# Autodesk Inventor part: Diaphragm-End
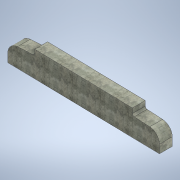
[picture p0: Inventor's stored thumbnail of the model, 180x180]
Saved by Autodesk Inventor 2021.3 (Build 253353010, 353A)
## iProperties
Created: 2021-10
Part Number: Diaphragm-End
Material: Concrete, Precast
Document SubType Name: Modeling
Designer: u1426
Density: 2.40731 g/cm^3
Appearance: Smooth Precast Structural
Author: u1426
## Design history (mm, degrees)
sketch "Sketch1"
  geometry: L1 (-762, 1295.4)-(-762, 1261.45); L2 (-726.164, 1223.417)-(-419.726, 1205.177); L3 (-228.6, 1002.336)-(-228.6, 838.2); L4 (-3225.8, 901.192)-(-3225.8, 1065.328); L5 (-2692.4, 1324.442)-(-2692.4, 1358.392); L6 (-2728.236, 1286.409)-(-3034.674, 1268.169); L7 (-3225.8, 901.192)-(-228.6, 838.2); L8 (-3302, 1358.392)-(-3302, 215.392); L9 (-152.4, 1295.4)-(-152.4, 152.4); L10 (-2692.4, 1358.392)-(-3302, 1358.392); L11 (-762, 1295.4)-(-152.4, 1295.4); L12 (-3302, 215.392)-(-4872.129, 215.392); L13 (-152.4, 152.4)-(-1248.139, 152.4); L14 (-2692.4, 1358.392)-(-2692.4, 1396.492); L15 (-2692.4, 1396.492)-(-762, 1355.921); L16 (-762, 1355.921)-(-762, 1295.4); A1 r 203.2 centre (-431.8, 1002.336) between (-228.6, 1002.336) and (-419.726, 1205.177); A2 r 38.1 centre (-723.9, 1261.45) between (-762, 1261.45) and (-726.164, 1223.417); A3 r 203.2 centre (-3022.6, 1065.328) between (-3034.674, 1268.169) and (-3225.8, 1065.328); A4 r 38.1 centre (-2730.5, 1324.442) between (-2728.236, 1286.409) and (-2692.4, 1324.442); 5 further points
  constraints: 32 end point, 8 point on circle, 8 point on line, 8 tangent, 5 vertical, 4 centre point, 2 horizontal, 2 parallel, 2 perpendicular
  dimensions: "d12" = 69.85 distance of L1.start point (-762, 1225.55); "d16" = 31.75 vertical distance of point (-762, 1225.55) point (-228.6, 1193.8); "d23" = 203.2 radius of A1; "d24" = 38.1 radius of A2; "d68" = 533.4 horizontal distance of point (-2692.4, 1288.542) point (-3225.8, 1256.792); "d69" = 31.75 vertical distance of point (-2692.4, 1288.542) point (-3225.8, 1256.792); "d70" = 69.85 distance of point (-2692.4, 1288.542) L5.end; "d78" = 203.2 radius of A3; "d79" = 38.1 radius of A4; "d82" = 76.2 distance between parallel lines of L3 L9; "d83" = 76.2 distance between parallel lines of L4 L8; "d84" = 1143 distance of L9.start L9.end; "d85" = 1143 distance of L8.start L8.end (= d84); "d88" = 62.992 distance between parallel lines of L13 L12 (= 0.02 x d89); "d89" = 3149.6 distance between parallel lines of L9 L8; "d90" = 38.1 distance of L5.end L14.end; "d91" = 152.4 distance from line of point (0, 0) L13; "d92" = 152.4 distance from line of point (0, 0) L9; "d93" = 533.4 distance between parallel lines of L3 L1; "d96" = 457.2 distance from line of L3.end L11; "d97" = 457.2 distance from line of L4.start L10 (= d96)
extrude "Extrusion9" new body sketch "Sketch1" stored distance "d94" = 254; taper "d95" = 0 deg
body "Solid4"
